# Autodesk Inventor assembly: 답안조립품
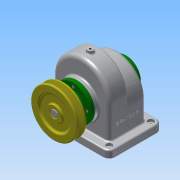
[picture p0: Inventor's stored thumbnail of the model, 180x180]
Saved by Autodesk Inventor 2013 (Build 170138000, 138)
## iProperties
Created: 2017-11
Part Number: 답안조립품
Document SubType Name: Assembly
Designer: Administrator
Author: Administrator
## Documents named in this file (14)
- C:\Users\Administrator\Desktop\471108V1011\답안조립품.iam
- C:\Users\Administrator\Desktop\471108V1011\본체.ipt
- C:\Users\Administrator\Desktop\471108V1011\V-벨트풀리.ipt
- C:\Users\Administrator\Desktop\471108V1011\뒤커버.ipt
- C:\Users\Administrator\Desktop\471108V1011\멈춤나사 - M4 x 10.ipt
- 멈춤나사 - M4 x 10.ipt
- C:\Users\Administrator\Desktop\471108V1011\베어링 6002.ipt
- C:\Users\Administrator\Desktop\471108V1011\볼트 M3 x 8.ipt
- C:\Users\Administrator\Desktop\471108V1011\스퍼기어.ipt
- C:\Users\Administrator\Desktop\471108V1011\앞커버.ipt
- C:\Users\Administrator\Desktop\471108V1011\오일 실 15 30 7.ipt
- C:\Users\Administrator\Desktop\471108V1011\축.ipt
- C:\Users\Administrator\Desktop\471108V1011\키 - 5 x 5 x 18.ipt
- C:\Users\Administrator\Desktop\471108V1011\키 - 6 x 6 x 22.ipt
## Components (1 placed, 1 different names)
1. V-벨트풀리:1
